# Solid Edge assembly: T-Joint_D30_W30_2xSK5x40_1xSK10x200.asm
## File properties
Author: fknapp
Template: iso metric assembly.asm
Last saved by: fknapp
Revision: 5
Application: Solid Edge
Username: fknapp
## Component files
T-Joint_D30_W30.par
SK Schraube 5x40_ohne_Gewinde.par
SK Schraube 10x200_ohne_Gewinde_22042020.par
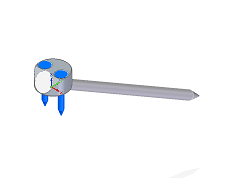
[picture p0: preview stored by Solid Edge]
